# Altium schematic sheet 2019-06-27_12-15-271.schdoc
size 359 x 127 mm; SheetNumber: 1; SheetTotal: 1
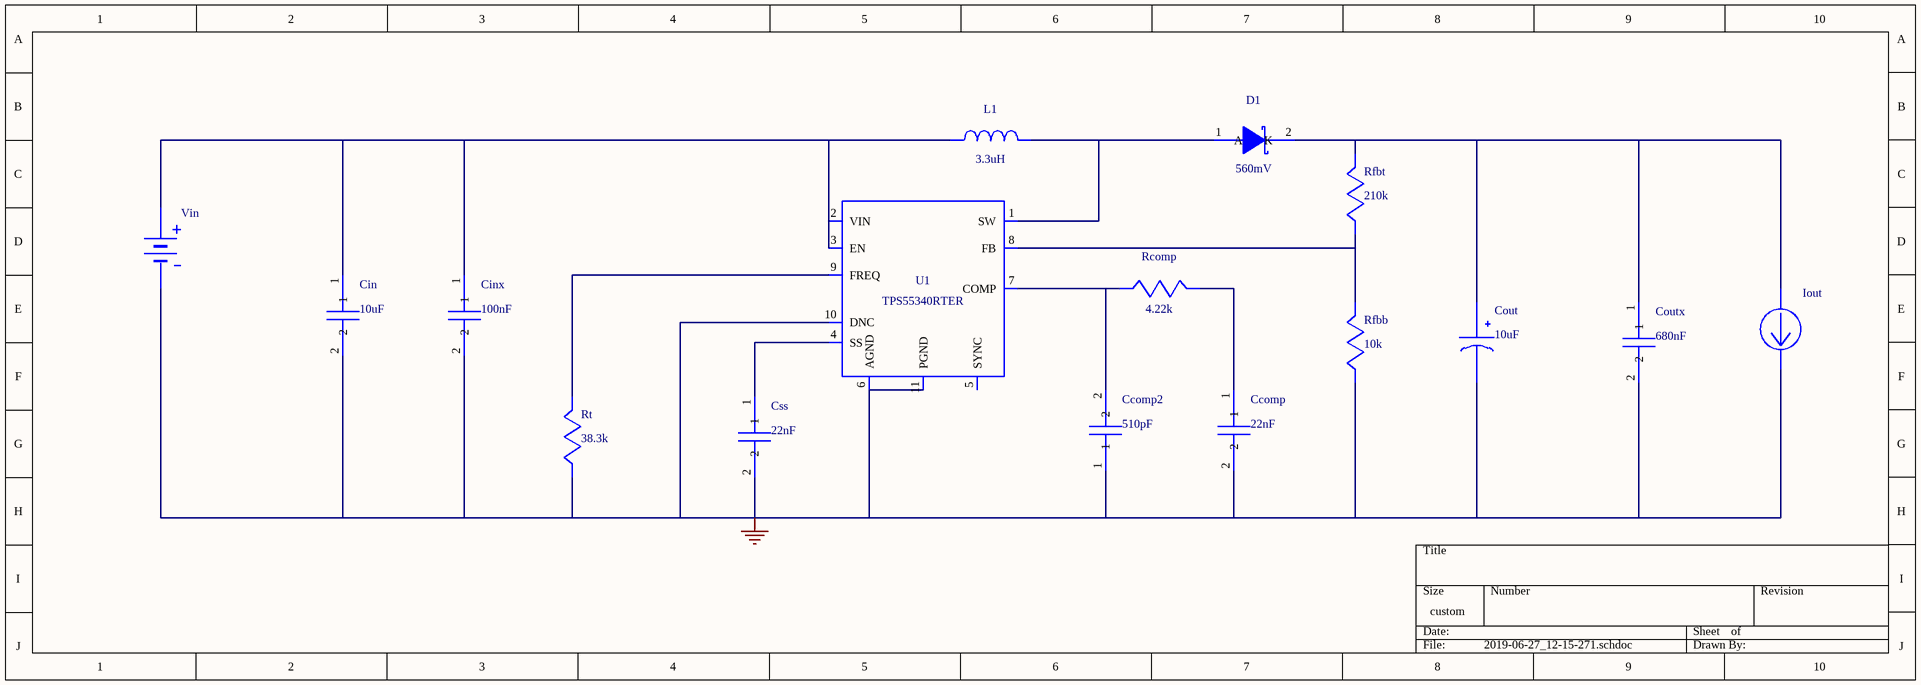
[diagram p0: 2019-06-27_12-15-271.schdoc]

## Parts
Ccomp  value 22nF  (hidden comment: GCM21B5C1H223JA16L)
Ccomp2  value 510pF  (hidden comment: CL21C511JBANNNC)
Cin  value 10uF  (hidden comment: GRM31CR61C106KA88L)
Cinx  value 100nF  (hidden comment: C0805C104M5RACTU)
Cout  value 10uF  (hidden comment: EEHZA1H100R)
Coutx  value 680nF  (hidden comment: GRM31MR72A684KA35L)
Css  value 22nF  (hidden comment: C2012C0G1E223J125AA)
D1  value 560mV  (hidden comment: PDS760-13)
Iout  WB_CURRENT_LOAD  (value not drawn)
L1  value 3.3uH  (hidden comment: XAL5030-332MEB)
Rcomp  value 4.22k  (hidden comment: ERJ-6ENF4221V)
Rfbb  value 10k  (hidden comment: CRCW080510K0FKEA)
Rfbt  value 210k  (hidden comment: ERJ-6ENF2103V)
Rt  value 38.3k  (hidden comment: CRCW080538K3FKEA)
U1  TPS55340RTER
Vin  WB_BATTERY  (value not drawn)

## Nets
0: Ccomp.2 Ccomp2.1 Cin.2 Cinx.2 Cout.2(-) Coutx.2 Css.2 Iout.2(-) Rfbb.2 Rt.2 U1.6(AGND) U1.10(DNC) U1.11(PGND) U1.12(PGND) U1.13(PGND) U1.14(DNC) U1.17(ETPAD) Vin.2(-)
NetCcomp2_2: Ccomp2.2 Rcomp.2 U1.7(COMP)
NetCcomp_1: Ccomp.1 Rcomp.1
NetCin_1: Cin.1 Cinx.1 L1.2 U1.2(VIN) U1.3(EN) Vin.1(+)
NetCout_1: Cout.1(+) Coutx.1 D1.2(K) Iout.1(+) Rfbt.1
NetCss_1: Css.1 U1.4(SS)
NetD1_1: D1.1(A) D1.3(A) L1.1 U1.1(SW) U1.15(SW) U1.16(SW)
NetRfbb_1: Rfbb.1 Rfbt.2 U1.8(FB)
NetRt_1: Rt.1 U1.9(FREQ)

Not connected (* = marked no-connect by the designer): U1 5(SYNC)

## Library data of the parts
Ccomp = GCM21B5C1H223JA16L: GCM21B5C1H223JA1; Manufacturer Name: MuRata
Ccomp2 = CL21C511JBANNNC: Manufacturer Name: Samsung Electro-Mechanics
Cin = GRM31CR61C106KA88L: GRM31CR61C106KA8; Manufacturer Name: MuRata
Cinx = C0805C104M5RACTU: Manufacturer Name: Kemet
Cout = EEHZA1H100R: Manufacturer Name: Panasonic
Coutx = GRM31MR72A684KA35L: GRM31MR72A684KA3; Manufacturer Name: MuRata
Css = C2012C0G1E223J125AA: C2012C0G1E223J12; Manufacturer Name: TDK
D1 = PDS760-13: Manufacturer Name: Diodes Inc.
L1 = XAL5030-332MEB: Manufacturer Name: Coilcraft
Rcomp = ERJ-6ENF4221V: Manufacturer Name: Panasonic
Rfbb = CRCW080510K0FKEA: Manufacturer Name: Vishay-Dale
Rfbt = ERJ-6ENF2103V: Manufacturer Name: Panasonic
Rt = CRCW080538K3FKEA: Manufacturer Name: Vishay-Dale
U1 = TPS55340RTER: Manufacturer Name: Texas Instruments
